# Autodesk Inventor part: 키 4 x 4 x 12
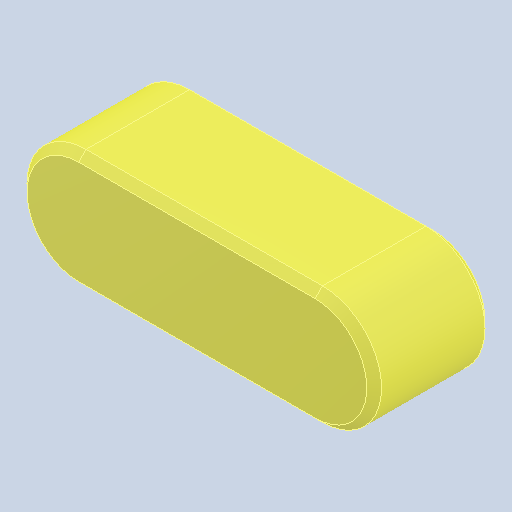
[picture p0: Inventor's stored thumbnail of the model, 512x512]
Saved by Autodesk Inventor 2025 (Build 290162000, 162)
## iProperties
Created: 2024-07
Part Number: 키 4 x 4 x 12
Material: 강철, 연강
Description: 키 및 해당 키홈
Document SubType Name: Modeling
Designer: onair
Density: 7.85 g/cm^3
Appearance: 기본값
Author: jhkim
Sending System: Autodesk Inventor 2025
Preprocessor: ST-DEVELOPER v20
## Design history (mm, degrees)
feature "Solid1"
node "솔리드1"
